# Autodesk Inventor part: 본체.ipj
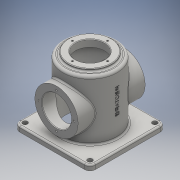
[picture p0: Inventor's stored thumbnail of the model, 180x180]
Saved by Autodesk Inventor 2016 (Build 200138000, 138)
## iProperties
Created: 2019-08
Part Number: 본체.ipj
Material: 일반
Document SubType Name: Modeling
Designer: user
Density: 1 g/cm^3
Appearance: 기본값
Author: user
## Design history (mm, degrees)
sketch "스케치1"
  geometry: L1 (-70, -70)-(70, -70); L2 (70, -70)-(70, 70); L3 (70, 70)-(-70, 70); L4 (-70, 70)-(-70, -70); L5 (-70, -70)-(70, 70); L6 (70, -70)-(-70, 70); 1 further point
  constraints: 12 end point, 2 midpoint, 2 parallel, 1 horizontal, 1 perpendicular
  dimensions: "d0" = 140 distance of L3.end L2.end; "d1" = 140 distance of L2.end L1.end
extrude "돌출1" new body sketch "스케치1" distance "d2" = 10; taper "d3" = 0 deg
sketch "스케치2"
  geometry: C1 r 50 at (0, 0); 1 further point
  constraints: 1 centre point, 1 coincident
  dimensions: "d4" = 100 diameter of C1
extrude "돌출2" join sketch "스케치2" distance "d5" = 110; taper "d6" = 0 deg
node "작업 평면1"
sketch "스케치4"
  geometry: L1 (-50, 10)-(50, 10) reference; L2 (70, 0)-(-70, 0) reference; C1 r 40 at (0, 60); 1 further point
  constraints: 1 centre point, 1 vertical alignment
  dimensions: "d8" = 80 diameter of C1; "d89" = 60 distance from line of L2 C1.centre
extrude "돌출3" join sketch "스케치4" stored distance "d10" = 110; taper "d11" = 0 deg
sketch "스케치5"
  geometry: C1 r 27 at (0, 0); 1 further point
  constraints: 1 centre point
  dimensions: "d12" = 54 diameter of C1
extrude "돌출4" cut sketch "스케치5" stored distance "d13" = 110; taper "d14" = 0 deg
sketch "스케치6" dims "d15" = 65
  geometry: 3 further points
  constraints: 1 vertical alignment, 2 other
hole "구멍1" sketch "스케치6" at (0, 32.5) diameter "d16" = 3.242; stored, may be unused: countersink angle "d20" = 90 deg, drill point angle "d22" = 118 deg; dims "d17" = 8, "d18" = 4, "d19" = 2, "d21" = 10
sketch "스케치7"
  geometry: C1 r 40 at (0, 0); 1 further point
  constraints: 1 centre point, 1 coincident
  dimensions: "d26" = 80 diameter of C1
extrude "돌출5" join sketch "스케치7" distance "d27" = 5; taper "d28" = 0 deg
sketch "스케치10"
  geometry: C1 r 27 at (0, 0); 1 further point
  constraints: 1 centre point, 1 coincident
  dimensions: "d29" = 54 diameter of C1
extrude "돌출6" cut sketch "스케치10" distance "d30" = 13; taper "d31" = 0 deg
sketch "스케치11" dims "d32" = 65
  geometry: 3 further points
  constraints: 1 coincident, 1 vertical alignment, 2 other
hole "구멍2" sketch "스케치11" at (0, 32.5) diameter "d33" = 3.242; stored, may be unused: countersink angle "d37" = 90 deg, drill point angle "d39" = 118 deg; dims "d34" = 8, "d35" = 4, "d36" = 2, "d38" = 10
fillet "모깎기1" dims "d43" = 10
hole "구멍3" diameter "d46" = 9; stored, may be unused: countersink angle "d50" = 90 deg, drill point angle "d52" = 0 deg; dims "d47" = 8, "d48" = 4, "d49" = 2, "d51" = 9, "d87" = 10, "d88" = 10
sketch "스케치12"
  geometry: C1 r 45 at (0, 0); 1 further point
  constraints: 1 centre point, 1 coincident
  dimensions: "d59" = 90 diameter of C1
extrude "돌출7" cut sketch "스케치12" distance "d60" = 112; taper "d61" = 0 deg
chamfer "모따기2" distance "d65" = 1; stored, may be unused: second distance "d66" = 2, angle "d67" = 45 deg
chamfer "모따기3" distance "d68" = 1; stored, may be unused: second distance "d69" = 2, angle "d70" = 45 deg
fillet "모깎기2" dims "d71" = 3
fillet "모깎기3" dims "d72" = 5
fillet "모깎기4" dims "d73" = 3
chamfer "모따기4" distance "d74" = 1; stored, may be unused: second distance "d75" = 2, angle "d76" = 45 deg
fillet "모깎기5" dims "d77" = 3
node "작업 평면5"
node "작업 평면6"
sketch "스케치19" dims "d0" = 140, "d1" = 140
  geometry: 2 further points
  constraints: 1 vertical alignment, 1 other
  dimensions: "d90" = 70 distance of point (0, 70) point (0, 0)
feature "엠보싱2" sketch "스케치19" dims "d0" = 140, "d1" = 140, "d85" = 0.5, "d86" = 0
node "솔리드1"
mirror "대칭1"
pattern_circular "원형 패턴1" dims angle "d24" = 360 deg
mirror "대칭2"
pattern_circular "원형 패턴2" dims angle "d41" = 360 deg
pattern_linear "직사각형 패턴1" dims "d55" = 120
other parameters: "d7" = -62, "d83" = 99.5, "d84" = 75
